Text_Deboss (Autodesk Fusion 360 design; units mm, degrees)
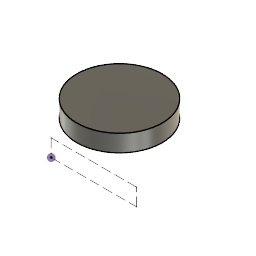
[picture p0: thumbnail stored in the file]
part number: 2026-08-31-14-48-55-015
sketch "Sketch1" plane through (0, 0, 0) normal (0, 0, 1) x axis (1, 0, 0)
  circle C1 centre (0, 0) radius 75
  point P1 (0, 0)
  point P2 (0, 0)
  coincident P1 P2
  dimension "d1" diameter C1 = 150
extrude "Extrude1" new body sketch "Sketch1" along normal blind 30
work_plane "WorkPlane1" AlongDistance -120 ExtraOffset 0
sketch "Text" plane through (0, -120, 0) normal (0, 1, 0) x axis (1, 0, 0)
  line L1 (150, 0) -> (0, 0)
  line L2 (150, -30) -> (150, 0)
  line L3 (0, -30) -> (150, -30)
  line L4 (0, 0) -> (0, -30)
  point P1 (0, 0)
  point P2 (0, 0)
  point P3 (150, 0)
  point P5 (0, -30)
  horizontal L1
  vertical L2
  horizontal L3
  vertical L4
  coincident P1 P2
  dimension "d6" distance P2 P3 = 150
  dimension "d7" distance P2 P5 = 30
